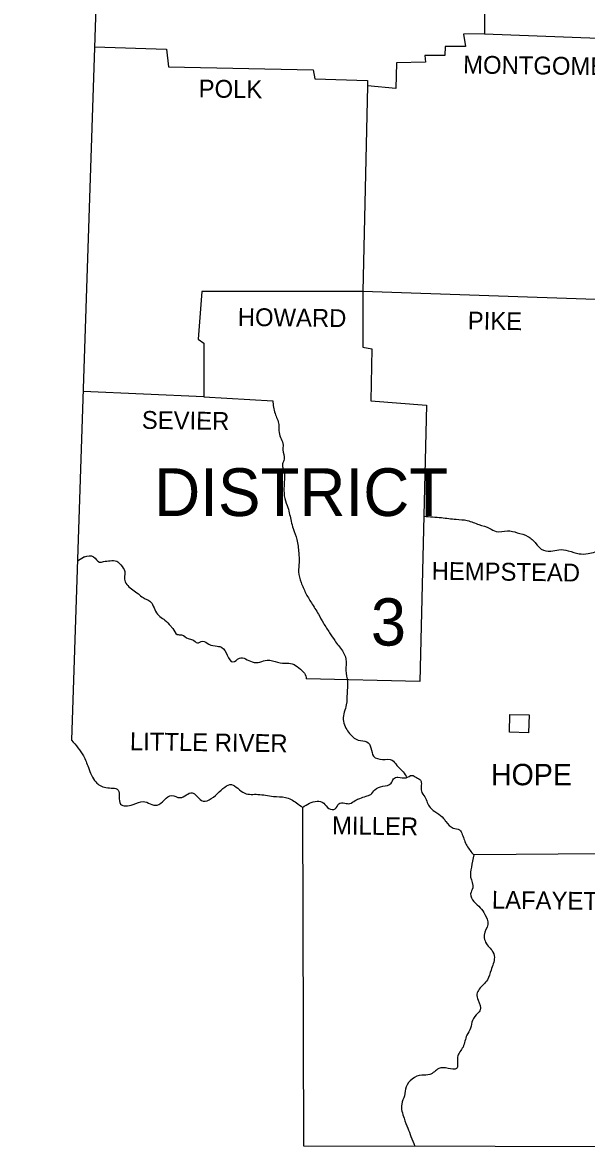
# Model space of a CAD drawing. Extents: x -0.25 to 1.92, y 0 to 0.95.
# Drawn here: x 1.0951 to 1.1566, y 0.5736 to 0.6965 of the extents above; entities that cross this region are included whole.
import ezdxf

# ---------------------------------------------------------------- set-up
doc = ezdxf.new("R2010")
doc.units = 0
doc.layers.add('Default', color=7, linetype='Continuous')

msp = doc.modelspace()

# ---------------------------------------------------------------- linework, layer by layer
at = {"layer": 'Default'}
msp.add_line((1.10185, 0.63817), (1.10109, 0.63769), dxfattribs=at)
for points in [[(1.09511, 0.81784), (1.10455, 0.74198), (1.10045, 0.61817)], [(1.14558, 0.71393), (1.14552, 0.69525), (1.14321, 0.6952), (1.14342, 0.69385), (1.14122, 0.69387), (1.14116, 0.69286), (1.13901, 0.69286), (1.13906, 0.69216), (1.1359, 0.69206), (1.13582, 0.68928), (1.13274, 0.68957), (1.13222, 0.66711)], [(1.14552, 0.69525), (1.16368, 0.69454)], [(1.10295, 0.69382), (1.11082, 0.69356), (1.11103, 0.69164), (1.1268, 0.69131), (1.12698, 0.69032), (1.13274, 0.69014), (1.13274, 0.68957)], [(1.15867, 0.6662), (1.13222, 0.66711), (1.11466, 0.66714), (1.11427, 0.66192), (1.11489, 0.66148), (1.11487, 0.65562), (1.10171, 0.65622)], [(1.13222, 0.66711), (1.13222, 0.66104), (1.13323, 0.66086), (1.13312, 0.65521), (1.13919, 0.65471), (1.13844, 0.62458), (1.12604, 0.62486)], [(1.11487, 0.65562), (1.12241, 0.65521)], [(1.12566, 0.61083), (1.12576, 0.5739), (1.29301, 0.57362)], [(1.16519, 0.603), (1.15846, 0.60339), (1.15815, 0.60578), (1.14433, 0.60565)]]:
    msp.add_lwpolyline(points, dxfattribs=at)
msp.add_lwpolyline([(1.14822, 0.61903), (1.14827, 0.62097), (1.15037, 0.62092), (1.15032, 0.61898)], close=True, dxfattribs=at)
for points in [[(1.12241, 0.65521), (1.12265, 0.65383), (1.12306, 0.65261), (1.12309, 0.65173), (1.12353, 0.65036), (1.1235, 0.64986), (1.12366, 0.64883), (1.12348, 0.64831), (1.12368, 0.64722), (1.12366, 0.64636), (1.12363, 0.64569), (1.12371, 0.64455), (1.12405, 0.64354), (1.12441, 0.64206), (1.12464, 0.64125), (1.12503, 0.64006), (1.12524, 0.63861), (1.12529, 0.63755), (1.12521, 0.63653), (1.1255, 0.63539), (1.12599, 0.63425), (1.12662, 0.63316), (1.12739, 0.63192), (1.12794, 0.63093), (1.12861, 0.62989), (1.12916, 0.62904), (1.13001, 0.62792), (1.13038, 0.62702), (1.13038, 0.62577), (1.13056, 0.62455), (1.13051, 0.62326), (1.13043, 0.62204), (1.13009, 0.62043), (1.1303, 0.61965), (1.13118, 0.61851), (1.13172, 0.61817), (1.13268, 0.61799), (1.13312, 0.61734), (1.13341, 0.61641), (1.13437, 0.61607), (1.13543, 0.61599), (1.13595, 0.61542), (1.13663, 0.6147), (1.13704, 0.61409)], [(1.13889, 0.6426), (1.1408, 0.64245), (1.14241, 0.64227), (1.14363, 0.64214), (1.1449, 0.64169), (1.14607, 0.64128), (1.14679, 0.64094), (1.14801, 0.64102), (1.14907, 0.64081), (1.15024, 0.6404), (1.15112, 0.63962), (1.15169, 0.63902), (1.15273, 0.63879), (1.15361, 0.63895), (1.15465, 0.63884), (1.15582, 0.63851), (1.1568, 0.63853), (1.15758, 0.63871), (1.15849, 0.63892), (1.1596, 0.63905), (1.16046, 0.63884), (1.1616, 0.63882), (1.16295, 0.63892), (1.16478, 0.63912)], [(1.10185, 0.63817), (1.10286, 0.63819), (1.10351, 0.6376), (1.10395, 0.63765), (1.10465, 0.63775), (1.10538, 0.6377), (1.10584, 0.63729), (1.10626, 0.63659), (1.10623, 0.63589), (1.10626, 0.6356), (1.10659, 0.63503), (1.10714, 0.63456), (1.10774, 0.63412), (1.10825, 0.63373), (1.10919, 0.63316), (1.10929, 0.63298), (1.10963, 0.63223), (1.1101, 0.63166), (1.11064, 0.63127), (1.11124, 0.63065), (1.1115, 0.63036), (1.11196, 0.62971), (1.11246, 0.62966), (1.11318, 0.62925), (1.11367, 0.62912), (1.11419, 0.62878), (1.11474, 0.62896), (1.11544, 0.62865), (1.11635, 0.62842), (1.11686, 0.62829), (1.11743, 0.62743), (1.11806, 0.6267), (1.11876, 0.62712), (1.12016, 0.6267), (1.12101, 0.62668), (1.12179, 0.62691), (1.12239, 0.62683), (1.12348, 0.62658), (1.12415, 0.62658), (1.1249, 0.62632), (1.12558, 0.62577), (1.12602, 0.62515), (1.12604, 0.62486)], [(1.10045, 0.61817), (1.10174, 0.61646), (1.10229, 0.61519), (1.10309, 0.61361), (1.10421, 0.61299), (1.10553, 0.61273), (1.10579, 0.6112), (1.10716, 0.61114), (1.10828, 0.61148), (1.10978, 0.61107), (1.11139, 0.61213), (1.1123, 0.6119), (1.1136, 0.61244), (1.11463, 0.61159), (1.11637, 0.61234), (1.1179, 0.61332), (1.11935, 0.61239), (1.12078, 0.61226), (1.12247, 0.61203), (1.12379, 0.61192), (1.12498, 0.61135), (1.12566, 0.61083)], [(1.12566, 0.61083), (1.12724, 0.61151), (1.12796, 0.6113), (1.12853, 0.6107), (1.12923, 0.61068), (1.1296, 0.61122), (1.13027, 0.6113), (1.13082, 0.61125), (1.13141, 0.61159), (1.13191, 0.61182), (1.13258, 0.61205), (1.1331, 0.61226), (1.13354, 0.61275), (1.1344, 0.61314), (1.13533, 0.61348), (1.13559, 0.61395), (1.13606, 0.61413), (1.13696, 0.61407), (1.13759, 0.61433), (1.13808, 0.6141), (1.13852, 0.61379), (1.13862, 0.61262), (1.13899, 0.61197), (1.13956, 0.61083), (1.14031, 0.61024), (1.14103, 0.60964), (1.14129, 0.60928), (1.1421, 0.60858), (1.14277, 0.60837), (1.14308, 0.60788), (1.14358, 0.60666), (1.14433, 0.60565)], [(1.14433, 0.60565), (1.14407, 0.6043), (1.14399, 0.60323), (1.14422, 0.60204), (1.14399, 0.60142), (1.14435, 0.60056), (1.14505, 0.59989), (1.14555, 0.59916), (1.14586, 0.59807), (1.14547, 0.59691), (1.14591, 0.59569), (1.14633, 0.59522), (1.14658, 0.59447), (1.14622, 0.59309), (1.14583, 0.59203), (1.14492, 0.59099), (1.14467, 0.59047), (1.1448, 0.5898), (1.14503, 0.58871), (1.14477, 0.58837), (1.1442, 0.5876), (1.14399, 0.58674), (1.14358, 0.58599), (1.14316, 0.58469), (1.14256, 0.58358), (1.14246, 0.58233), (1.14153, 0.58236), (1.14052, 0.58233), (1.13953, 0.58168), (1.13867, 0.58163), (1.13761, 0.58119), (1.13696, 0.58033), (1.13676, 0.57937), (1.13647, 0.57847), (1.13673, 0.57691), (1.13714, 0.57582), (1.13748, 0.57494), (1.13792, 0.57388)]]:
    msp.add_spline(points, degree=3, dxfattribs=at)

# ---------------------------------------------------------------- texts
for s, height, rotation, p in [('MONTGOMERY', 0.001945, 359.2707, (1.14317, 0.69092)), ('POLK', 0.001945, 359.3233, (1.11431, 0.6883)), ('HOWARD', 0.001945, 359.303, (1.11858, 0.66338)), ('PIKE', 0.001945, 359.1737, (1.14367, 0.66299)), ('SEVIER', 0.001945, 359.1815, (1.10811, 0.65215)), ('HEMPSTEAD', 0.001945, 359.2571, (1.13973, 0.63568)), ('LITTLE RIVER', 0.0019451, 359.2076, (1.10681, 0.61708)), ('MILLER', 0.001945, 359.1885, (1.12886, 0.60791)), ('LAFAYETTE', 0.001945, 359.2511, (1.1463, 0.59979))]:
    msp.add_text(s, height=height, rotation=rotation, dxfattribs=at).set_placement(p)
for s, height, p in [('DISTRICT', 0.005203, (1.10947, 0.64263)), ('3', 0.00516, (1.13311, 0.62849)), ('HOPE', 0.002334, (1.1462, 0.61325))]:
    msp.add_text(s, height=height, dxfattribs=at).set_placement(p)

doc.saveas('drawing.dxf')
